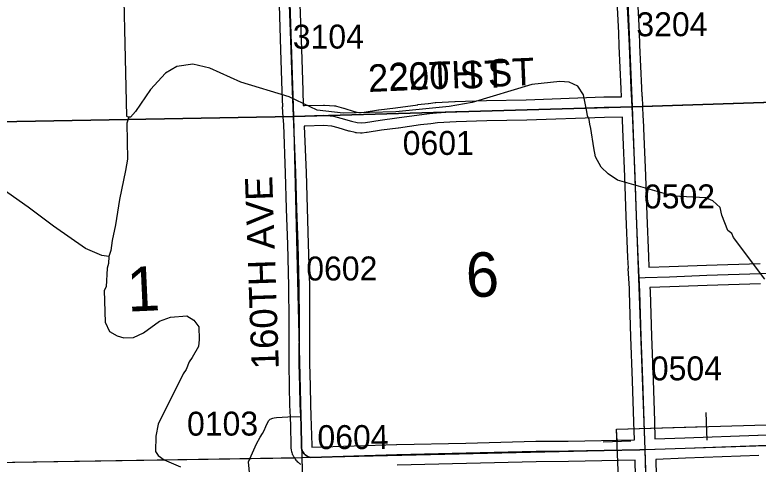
# Model space of a CAD drawing. Extents: x 128.7 to 185.5, y -21.4 to 12.6.
# Drawn here: x 139.361 to 141.537, y -8.565 to -7.251 of the extents above; entities that cross this region are included whole.
import ezdxf

# ---------------------------------------------------------------- set-up
doc = ezdxf.new("R2010")
doc.units = 0
for name, color, linetype in [('tdCoHydroRiver', 7, 'Continuous'), ('tdCoPipe', 7, 'Continuous'), ('tdCoSecRdNmbr', 7, 'Continuous'), ('tdCoSecRdTxt', 7, 'Continuous'), ('tdCoSecRteBand', 7, 'Continuous'), ('tdCoSecRteCL', 7, 'Continuous'), ('tdCoSectLine', 7, 'Continuous'), ('tdCoSectLinePart', 7, 'Continuous'), ('tdCoSectNmbr', 7, 'Continuous'), ('tdCoSurfAsphalt', 7, 'Continuous'), ('tdCoSurfGravel', 7, 'Continuous'), ('tdCoSurfLNO', 7, 'Continuous'), ('tdCoTwpBndry', 7, 'Continuous'), ('tdCoTwpBndryShd', 7, 'Continuous')]:
    doc.layers.add(name, color=color, linetype=linetype)

msp = doc.modelspace()

# ---------------------------------------------------------------- linework, layer by layer
at = {"layer": 'tdCoHydroRiver'}
for points in [[(139.6752, -6.9968), (139.6877, -7.5472), (139.6941, -7.5501), (139.6883, -7.5677), (139.69, -7.6733), (139.6848, -7.7066), (139.6669, -7.7908), (139.655, -7.8654), (139.6454, -7.9115), (139.6416, -7.94), (139.6358, -7.9575), (139.6349, -7.9781), (139.6306, -7.9924), (139.6275, -8.0462), (139.6216, -8.0574), (139.6245, -8.1504), (139.6379, -8.1768), (139.6604, -8.1903), (139.6795, -8.196), (139.7079, -8.1951), (139.7375, -8.1816), (139.7837, -8.147), (139.8165, -8.1349), (139.8638, -8.1319), (139.8846, -8.1439), (139.8995, -8.1639), (139.9006, -8.2002), (139.8981, -8.2208), (139.8802, -8.2529), (139.8711, -8.2658), (139.8623, -8.2882), (139.8533, -8.3011), (139.7805, -8.4485), (139.7737, -8.4835), (139.772, -8.5277), (139.7802, -8.5401), (139.798, -8.5521), (139.846, -8.5727)], [(141.5569, -8.0238), (141.4647, -7.902), (141.4596, -7.8911), (141.4483, -7.882), (141.4311, -7.8367), (141.4257, -7.8148), (141.4045, -7.795), (141.3838, -7.7861), (141.2889, -7.7812), (141.1249, -7.7343), (141.0975, -7.7162), (141.0779, -7.6963), (141.0612, -7.6668), (141.0557, -7.6401), (141.0476, -7.5836), (141.0441, -7.5711), (141.042, -7.5569), (141.037, -7.5461), (141.035, -7.5335), (141.0256, -7.4849), (141.009, -7.4601), (140.9834, -7.4483), (140.9565, -7.446), (140.8747, -7.4549), (140.6996, -7.5077), (140.6321, -7.5192), (140.4764, -7.5352), (140.3218, -7.5384), (140.2458, -7.5297), (140.1641, -7.4913), (140.0223, -7.4483), (139.9311, -7.407), (139.8818, -7.3959), (139.8347, -7.4021), (139.8021, -7.4221), (139.7579, -7.4692), (139.7141, -7.5337), (139.6988, -7.55), (139.6941, -7.5501)], [(139.6358, -7.9575), (139.6152, -7.955), (139.5672, -7.9344), (139.4737, -7.8695), (139.3993, -7.8134), (139.3235, -7.7605)]]:
    msp.add_lwpolyline(points, dxfattribs=at)
at = {"layer": 'tdCoPipe'}
for p, q in [((141.3877, -8.4952), (141.3854, -8.4146)), ((141.1641, -8.4977), (141.0837, -8.5009))]:
    msp.add_line(p, q, dxfattribs=at)
for points in [[(141.1601, -9.4052), (141.1224, -8.4625), (145.143, -8.3469), (145.1432, -8.4836), (145.1432, -8.4836), (147.1541, -8.3987), (147.1541, -8.3987), (147.1261, -7.4066), (149.2539, -7.3111), (149.2196, -6.4561), (150.4341, -6.4227), (150.6653, -6.4146), (150.7655, -6.4047), (150.7905, -6.3931), (150.9328, -6.2039), (151.0021, -6.1768), (151.0811, -6.1651), (151.2121, -6.1436), (151.4086, -6.1336), (151.5974, -6.1255), (151.7034, -6.1214)], [(141.1239, -8.4993), (141.1224, -8.4625), (141.3866, -8.4549)]]:
    msp.add_lwpolyline(points, dxfattribs=at)
at = {"layer": 'tdCoSecRteBand'}
for points in [[(140.3744, -7.5369), (140.3836, -7.536), (140.4253, -7.5292), (140.4259, -7.5292), (140.4264, -7.5291), (140.4755, -7.5229), (140.5401, -7.5139), (140.5404, -7.5138), (140.5407, -7.5138), (140.5713, -7.5101), (140.5714, -7.5101), (140.5716, -7.51), (140.5918, -7.5078), (140.5925, -7.5077), (140.5933, -7.5077), (140.6492, -7.5042), (140.6497, -7.5042), (140.6502, -7.5042), (140.7414, -7.5015), (140.7416, -7.5015), (140.7418, -7.5015), (140.8582, -7.4993), (141.0851, -7.4914), (141.0853, -7.4914), (141.0856, -7.4914), (141.1367, -7.4906), (141.1356, -7.4675), (141.1356, -7.4674), (141.1356, -7.4674), (141.1302, -7.3428), (141.1302, -7.3427), (141.1302, -7.3426), (141.1287, -7.3034), (141.1221, -7.1731)], [(141.182, -7.1702), (141.1886, -7.3005), (141.1887, -7.3007), (141.1887, -7.3009), (141.1901, -7.3403), (141.1956, -7.4647), (141.1967, -7.4887), (141.1968, -7.4896), (141.1977, -7.4896), (141.1982, -7.5191), (141.1996, -7.5486), (141.2, -7.5568), (141.2, -7.557), (141.2, -7.5571), (141.202, -7.6066), (141.2069, -7.7215), (141.2069, -7.7216), (141.2069, -7.7217), (141.2109, -7.8375), (141.2158, -7.9582), (141.2172, -7.9888)], [(140.1981, -8.5658), (140.1966, -8.5649), (140.1952, -8.5638), (140.1922, -8.5615), (140.1908, -8.5604), (140.1895, -8.5591), (140.1869, -8.5565), (140.1856, -8.5552), (140.1845, -8.5539), (140.1821, -8.5509), (140.181, -8.5495), (140.1801, -8.548), (140.1781, -8.5448), (140.1771, -8.5433), (140.1764, -8.5417), (140.1748, -8.5383), (140.174, -8.5367), (140.1735, -8.535), (140.1723, -8.5314), (140.1717, -8.5297), (140.1714, -8.528), (140.1706, -8.5243), (140.1703, -8.5225), (140.1701, -8.5207), (140.1698, -8.517), (140.1697, -8.5152), (140.1698, -8.5134), (140.1699, -8.5106), (140.1687, -8.454), (140.1676, -8.4273), (140.1662, -8.3924), (140.1662, -8.3921), (140.1662, -8.3919), (140.165, -8.3389), (140.165, -8.3389), (140.165, -8.3388), (140.1635, -8.271), (140.1635, -8.2707), (140.1635, -8.2703), (140.1637, -8.1481), (140.163, -8.045), (140.1598, -7.9228), (140.1561, -7.8182), (140.1561, -7.8181), (140.1561, -7.818), (140.1531, -7.7143), (140.1477, -7.5721), (140.1466, -7.5502), (140.1447, -7.5204), (140.1451, -7.5204), (140.1451, -7.52), (140.1451, -7.52), (140.1435, -7.4744), (140.1435, -7.4743), (140.1435, -7.4743), (140.1396, -7.3537), (140.1351, -7.2231)], [(140.1951, -7.221), (140.1995, -7.3517), (140.1995, -7.3517), (140.1995, -7.3518), (140.2035, -7.4723), (140.205, -7.5165), (140.2072, -7.5163), (140.2079, -7.5163), (140.2085, -7.5163), (140.2645, -7.515), (140.266, -7.515), (140.2674, -7.5151), (140.2963, -7.5174), (140.2992, -7.5176), (140.3021, -7.5184), (140.3233, -7.5243), (140.3235, -7.5244), (140.3237, -7.5244), (140.3543, -7.5335), (140.3676, -7.5365), (140.3744, -7.5369)], [(140.2305, -8.5152), (140.4784, -8.5079), (140.4785, -8.5079), (140.4786, -8.5079), (140.6815, -8.5035), (140.8862, -8.4983), (140.8864, -8.4983), (140.8867, -8.4983), (140.981, -8.4976), (141.1751, -8.4937), (141.1733, -8.4419), (141.1733, -8.4418), (141.1733, -8.4418), (141.1696, -8.3211), (141.1647, -8.1932), (141.1647, -8.1931), (141.1647, -8.193), (141.1605, -8.0623), (141.16, -8.0518), (141.1587, -8.0223), (141.1564, -7.9929), (141.1573, -7.9928), (141.1573, -7.9919), (141.1558, -7.9609), (141.1558, -7.9608), (141.1558, -7.9607), (141.1509, -7.8399), (141.1509, -7.8398), (141.1509, -7.8397), (141.147, -7.7239), (141.142, -7.6091), (141.142, -7.6091), (141.142, -7.609), (141.1401, -7.5596), (141.1396, -7.5505), (141.0869, -7.5514), (140.86, -7.5592), (140.8598, -7.5592), (140.8595, -7.5593), (140.7431, -7.5615), (140.6525, -7.5642), (140.5977, -7.5675), (140.5783, -7.5697), (140.5482, -7.5733), (140.4836, -7.5824), (140.4834, -7.5824), (140.4832, -7.5825), (140.4344, -7.5886), (140.3923, -7.5954), (140.3913, -7.5955), (140.3904, -7.5956), (140.3778, -7.5968), (140.3754, -7.5971), (140.373, -7.5969), (140.3614, -7.5962), (140.359, -7.596), (140.3567, -7.5955), (140.3402, -7.5918), (140.3392, -7.5916), (140.3382, -7.5913), (140.3069, -7.582), (140.2888, -7.5769), (140.2643, -7.5751), (140.2105, -7.5763), (140.208, -7.5764), (140.208, -7.5768), (140.2079, -7.5768), (140.2131, -7.7121), (140.2131, -7.7123), (140.2131, -7.7124), (140.2161, -7.8161), (140.2198, -7.9209), (140.2198, -7.921), (140.2198, -7.9211), (140.223, -8.0437), (140.223, -8.044), (140.223, -8.0443), (140.2237, -8.1478), (140.2237, -8.148), (140.2237, -8.1481), (140.2235, -8.2701), (140.2249, -8.3375), (140.2262, -8.3903), (140.2276, -8.4249), (140.2286, -8.4519), (140.2286, -8.4522), (140.2286, -8.4525), (140.2299, -8.5102), (140.2299, -8.511), (140.2299, -8.5119), (140.2298, -8.5139), (140.2298, -8.5141), (140.2298, -8.5143), (140.2299, -8.5145), (140.23, -8.5147), (140.2301, -8.5148), (140.2302, -8.515), (140.2304, -8.5151), (140.2305, -8.5152)], [(141.2172, -7.9888), (141.2764, -7.9871), (141.3861, -7.9828), (141.3862, -7.9828), (141.3863, -7.9828), (141.5426, -7.9782)], [(141.5445, -8.0381), (141.3882, -8.0428), (141.2786, -8.0471), (141.2784, -8.0471), (141.2783, -8.0471), (141.22, -8.0488), (141.2205, -8.0597), (141.2205, -8.0599), (141.2205, -8.0601), (141.2247, -8.191), (141.2296, -8.3189), (141.2296, -8.319), (141.2296, -8.3191), (141.2333, -8.4399), (141.235, -8.4915)], [(141.235, -8.4915), (141.322, -8.488), (141.322, -8.488), (141.3221, -8.488), (141.5367, -8.4803), (141.5368, -8.4803), (141.5369, -8.4803), (141.6707, -8.4766)], [(141.1802, -8.6659), (141.1773, -8.5592), (141.1771, -8.5537), (141.1771, -8.5537), (140.982, -8.5576), (140.9818, -8.5576), (140.9816, -8.5576), (140.8874, -8.5583), (140.683, -8.5635), (140.683, -8.5635), (140.6829, -8.5635), (140.4801, -8.5679)], [(141.5387, -8.5403), (141.3243, -8.5479), (141.2373, -8.5515), (141.2371, -8.5515), (141.2372, -8.5573), (141.2373, -8.5573), (141.2373, -8.5574), (141.2402, -8.6639)]]:
    msp.add_lwpolyline(points, dxfattribs=at)
at = {"layer": 'tdCoSecRteCL'}
for points in [[(141.1682, -7.5201), (141.1656, -7.466), (141.1602, -7.3415), (141.1587, -7.3021), (141.152, -7.1716), (141.1468, -7.053), (141.145, -7.0141)], [(140.1766, -7.5484), (140.1752, -7.5224), (140.1735, -7.4733), (140.1696, -7.3527), (140.1651, -7.222), (140.1602, -7.0686), (140.1593, -7.0472)], [(140.1766, -7.5484), (140.2092, -7.5463), (140.2651, -7.545), (140.294, -7.5473), (140.3152, -7.5532), (140.3468, -7.5626), (140.3633, -7.5663), (140.3749, -7.567), (140.3875, -7.5658), (140.4301, -7.5589), (140.4794, -7.5527), (140.5443, -7.5436), (140.5749, -7.5399), (140.5951, -7.5376), (140.6511, -7.5342), (140.7423, -7.5315), (140.859, -7.5293), (141.0861, -7.5214), (141.1682, -7.5201)], [(141.1886, -8.0205), (141.1858, -7.9595), (141.1809, -7.8387), (141.1769, -7.7228), (141.172, -7.6078), (141.17, -7.5583), (141.1682, -7.5201)], [(141.2061, -8.5227), (141.1905, -8.5234), (140.9814, -8.5276), (140.8869, -8.5283), (140.6822, -8.5335), (140.4793, -8.5379), (140.2275, -8.5453), (140.2238, -8.5446), (140.2202, -8.5435), (140.2168, -8.542), (140.2136, -8.5401), (140.2106, -8.5377), (140.2079, -8.5351), (140.2056, -8.5322), (140.2036, -8.529), (140.202, -8.5256), (140.2008, -8.522), (140.2, -8.5183), (140.1997, -8.5146), (140.1999, -8.5108), (140.1987, -8.4531), (140.1976, -8.4261), (140.1962, -8.3912), (140.195, -8.3382), (140.1935, -8.2704), (140.1937, -8.148), (140.193, -8.0445), (140.1898, -7.9219), (140.1861, -7.8171), (140.1831, -7.7133), (140.1777, -7.5707), (140.1766, -7.5484)], [(141.1886, -8.0205), (141.2063, -8.0191), (141.2774, -8.0171), (141.3872, -8.0128), (141.5436, -8.0081), (141.6294, -8.0054), (141.727, -8.0025), (141.8425, -7.9988), (141.9305, -7.9963), (142.0577, -7.9916), (142.1719, -7.9882), (142.2565, -7.9862), (142.3921, -7.9815), (142.533, -7.9771), (142.6664, -7.9736), (142.6902, -7.9727)], [(141.2061, -8.5227), (141.2033, -8.4409), (141.1996, -8.32), (141.1947, -8.1921), (141.1905, -8.0611), (141.1886, -8.0205)], [(141.2061, -8.5227), (141.3232, -8.518), (141.5377, -8.5103), (141.6716, -8.5066), (141.9713, -8.496), (142.1727, -8.4903), (142.2808, -8.4879), (142.5816, -8.4787), (142.7192, -8.4741), (142.8359, -8.4709), (142.9996, -8.4667), (143.1372, -8.4625), (143.2095, -8.4601)], [(141.2375, -9.5202), (141.2358, -9.4825), (141.2354, -9.473), (141.2347, -9.4512), (141.2333, -9.405), (141.233, -9.3966), (141.2324, -9.3785), (141.2312, -9.3403), (141.2295, -9.2618), (141.2258, -9.1361), (141.2221, -9.0367), (141.2184, -8.9228), (141.2152, -8.8014), (141.2127, -8.7144), (141.2102, -8.665), (141.2073, -8.5583), (141.2061, -8.5227)]]:
    msp.add_lwpolyline(points, dxfattribs=at)
at = {"layer": 'tdCoSectLine'}
for points in [[(141.126, -6.511), (141.1678, -7.5201)], [(140.1441, -6.552), (140.1762, -7.5484)], [(141.1678, -7.5201), (142.1753, -7.4874)], [(140.1762, -7.5484), (141.1678, -7.5201)], [(141.1678, -7.5201), (141.2057, -8.5227)], [(139.1499, -7.567), (140.1762, -7.5484)], [(140.1762, -7.5484), (140.2009, -8.5459)], [(141.2057, -8.5227), (142.2109, -8.4895)], [(140.2009, -8.5459), (141.2057, -8.5227)], [(141.2057, -8.5227), (141.2371, -9.5202)], [(139.1713, -8.5626), (140.2009, -8.5459)], [(140.2009, -8.5459), (140.2273, -9.5432)]]:
    msp.add_lwpolyline(points, dxfattribs=at)
at = {"layer": 'tdCoSectLinePart'}
for points in [[(141.1979, -7.5191), (142.1753, -7.4874)], [(139.1499, -7.567), (140.1464, -7.5489)], [(139.1713, -8.5626), (140.1788, -8.5463)]]:
    msp.add_lwpolyline(points, dxfattribs=at)
at = {"layer": 'tdCoSurfAsphalt'}
msp.add_lwpolyline([(141.2102, -8.665), (141.2073, -8.5583), (141.2061, -8.5227), (141.2033, -8.4409), (141.1996, -8.32), (141.1947, -8.1921), (141.1905, -8.0611), (141.1886, -8.0205), (141.1858, -7.9595), (141.1809, -7.8387), (141.1769, -7.7228), (141.172, -7.6078), (141.17, -7.5583), (141.1682, -7.5201), (141.1656, -7.466), (141.1602, -7.3415), (141.1587, -7.3021), (141.152, -7.1716)], dxfattribs=at)
at = {"layer": 'tdCoSurfGravel'}
for points in [[(140.1976, -8.4261), (140.1962, -8.3912), (140.195, -8.3382), (140.1935, -8.2704), (140.1937, -8.148), (140.193, -8.0445), (140.1898, -7.9219), (140.1861, -7.8171), (140.1831, -7.7133), (140.1777, -7.5707), (140.1766, -7.5484), (140.1752, -7.5224), (140.1735, -7.4733), (140.1696, -7.3527), (140.1651, -7.222)], [(140.1766, -7.5484), (140.2092, -7.5463), (140.2651, -7.545), (140.294, -7.5473), (140.3152, -7.5532), (140.3468, -7.5626), (140.3633, -7.5663), (140.3749, -7.567), (140.3875, -7.5658), (140.4301, -7.5589), (140.4794, -7.5527), (140.5443, -7.5436), (140.5749, -7.5399), (140.5951, -7.5376), (140.6511, -7.5342), (140.7423, -7.5315), (140.859, -7.5293), (141.0861, -7.5214), (141.1682, -7.5201)], [(141.1886, -8.0205), (141.2063, -8.0191), (141.2774, -8.0171), (141.3872, -8.0128), (141.5436, -8.0081)], [(140.1976, -8.4261), (140.1987, -8.4531), (140.1999, -8.5108), (140.1997, -8.5146), (140.2, -8.5183), (140.2008, -8.522), (140.202, -8.5256), (140.2036, -8.529), (140.2056, -8.5322), (140.2079, -8.5351), (140.2106, -8.5377), (140.2136, -8.5401), (140.2168, -8.542), (140.2202, -8.5435), (140.2238, -8.5446), (140.2275, -8.5453), (140.4793, -8.5379), (140.6822, -8.5335), (140.8869, -8.5283), (140.9814, -8.5276), (141.1905, -8.5234), (141.2061, -8.5227), (141.3232, -8.518), (141.5377, -8.5103)]]:
    msp.add_lwpolyline(points, dxfattribs=at)
at = {"layer": 'tdCoSurfLNO'}
for p, q in [((140.0951, -8.4555), (140.1029, -8.4386)), ((140.1029, -8.4386), (140.1085, -8.4334)), ((140.1085, -8.4334), (140.1157, -8.4306)), ((140.1157, -8.4306), (140.1195, -8.4297)), ((140.1195, -8.4297), (140.1267, -8.4283)), ((140.1267, -8.4283), (140.1598, -8.4263)), ((140.1598, -8.4263), (140.1976, -8.4261)), ((140.0908, -8.4672), (140.0951, -8.4555)), ((140.068, -8.5062), (140.0785, -8.4865)), ((140.0785, -8.4865), (140.0854, -8.4759)), ((140.0854, -8.4759), (140.0908, -8.4672)), ((140.0445, -8.5583), (140.068, -8.5062)), ((140.0488, -8.5997), (140.0445, -8.5583))]:
    msp.add_line(p, q, dxfattribs=at)
at = {"layer": 'tdCoTwpBndry'}
for points in [[(142.641, -7.4727), (142.1753, -7.4874), (141.1978, -7.5191)], [(140.1462, -7.549), (139.1499, -7.567), (138.1783, -7.5984), (137.2062, -7.6268)]]:
    msp.add_lwpolyline(points, dxfattribs=at)
at = {"layer": 'tdCoTwpBndryShd'}
for points in [[(139.7753, 4.488), (139.8117, 3.486), (139.847, 2.4824), (139.8814, 1.4767), (139.916, 0.4726), (139.9523, -0.532), (139.9867, -1.5369), (140.02, -2.5417), (140.0555, -3.5439), (140.0879, -4.5437), (140.1169, -5.5472), (140.1441, -6.552), (140.1762, -7.5484), (140.2009, -8.5459), (140.2273, -9.5432), (140.2527, -10.5463), (140.2854, -11.5456), (140.3203, -12.5525), (140.3446, -13.5481), (140.3501, -13.7735)], [(150.395, -13.7476), (150.378, -13.2238), (150.3466, -12.2212), (150.3134, -11.2212), (150.2794, -10.2174), (150.245, -9.219), (150.2118, -8.2199), (150.1854, -7.2186), (149.1912, -7.251), (148.1861, -7.2877), (147.1862, -7.3236), (146.1796, -7.3579), (145.1769, -7.3938), (144.1761, -7.4248), (143.1728, -7.4558), (142.1753, -7.4874), (141.1678, -7.5201), (140.1762, -7.5484), (139.1499, -7.567), (138.1783, -7.5984), (137.1762, -7.6276), (136.1739, -7.6508), (135.1725, -7.6763), (134.1612, -7.6994)]]:
    msp.add_lwpolyline(points, dxfattribs=at)

# ---------------------------------------------------------------- texts
at = {"layer": 'tdCoSecRdNmbr'}
for s, rotation, p in [('3204', 0.1073, (141.1806, -7.3139)), ('3104', 0.1066, (140.1745, -7.3501)), ('0601', 0.1068, (140.4963, -7.6611)), ('0502', 0.1073, (141.2026, -7.8174)), ('0602', 0.1066, (140.2139, -8.0282)), ('0504', 0.1073, (141.223, -8.3202)), ('0103', 0.1066, (139.8647, -8.4819)), ('0604', 0.1066, (140.2466, -8.5212))]:
    msp.add_text(s, height=0.07, rotation=rotation, dxfattribs=at).set_placement(p)
at = {"layer": 'tdCoSecRdTxt'}
for s, rotation, p in [('220TH ST', 2.4265, (140.3966, -7.4769)), ('220 ST', 1.4265, (140.4559, -7.472)), ('160TH AVE', 92, (140.1338, -8.2866))]:
    msp.add_text(s, height=0.08, rotation=rotation, dxfattribs=at).set_placement(p)
at = {"layer": 'tdCoSectNmbr'}
for s, rotation, p in [('6', 2.6592, (140.6841, -8.078)), ('1', 2.6585, (139.6913, -8.1194))]:
    msp.add_text(s, height=0.13, rotation=rotation, dxfattribs=at).set_placement(p)

doc.saveas('drawing.dxf')
